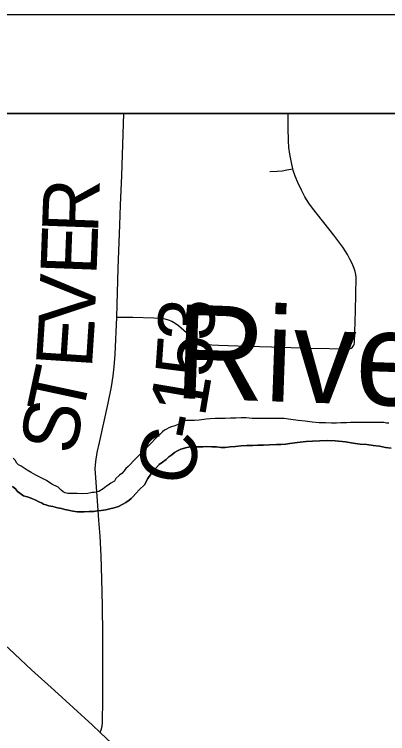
# Model space of a CAD drawing. Extents: x 0 to 34, y 0 to 22.
# Drawn here: x 25.806 to 26.184, y 20.273 to 21 of the extents above; entities that cross this region are included whole.
import ezdxf

# ---------------------------------------------------------------- set-up
doc = ezdxf.new("R2010")
doc.units = 0
for name, color, linetype in [('GM_X_County_Road', 7, 'Continuous'), ('GM_X_County_Road_Text', 7, 'Continuous'), ('GM_X_Major_River', 7, 'Continuous'), ('GM_X_Major_River_Text', 7, 'Continuous'), ('GM_X_State_Route', 7, 'Continuous'), ('GM_X_Township_Road', 7, 'Continuous'), ('SH_Data', 7, 'Continuous')]:
    doc.layers.add(name, color=color, linetype=linetype)

msp = doc.modelspace()

# ---------------------------------------------------------------- linework, layer by layer
at = {"layer": 'GM_X_County_Road'}
for points in [[(25.90978, 20.69411), (25.91088, 20.74343), (25.91264, 20.78688), (25.91344, 20.80738), (25.91462, 20.8372), (25.91676, 20.89997), (25.91676, 20.9)], [(25.8912, 20.49396), (25.88835, 20.532), (25.88788, 20.54084), (25.88833, 20.54822), (25.88979, 20.55737), (25.89217, 20.56749), (25.90082, 20.60711), (25.90424, 20.62359), (25.90597, 20.63468), (25.907, 20.64399), (25.90809, 20.65636), (25.90978, 20.69411)], [(25.89291, 20.27439), (25.89375, 20.27727), (25.89474, 20.28065), (25.89519, 20.28442), (25.89551, 20.30809), (25.89543, 20.33856), (25.89545, 20.37275), (25.89508, 20.40261), (25.89455, 20.42933), (25.89381, 20.45294), (25.89286, 20.47282), (25.89158, 20.48895), (25.8912, 20.49396)]]:
    msp.add_lwpolyline(points, dxfattribs=at)
at = {"layer": 'GM_X_Major_River'}
for points in [[(26.02465, 20.5919), (26.01933, 20.59166), (26.01401, 20.59179), (26.00907, 20.59154), (26.00412, 20.59128), (25.99994, 20.59101), (25.99308, 20.59005), (25.98813, 20.58979), (25.98357, 20.58953), (25.98015, 20.58961), (25.97786, 20.58929), (25.97516, 20.58746), (25.97169, 20.58565), (25.96824, 20.58422), (25.96479, 20.58317), (25.9621, 20.5821), (25.9598, 20.58102), (25.95787, 20.57993), (25.95593, 20.57808), (25.95359, 20.57586), (25.95088, 20.57365), (25.94814, 20.57069), (25.94502, 20.56735), (25.9415, 20.56364), (25.938, 20.56031), (25.93567, 20.5581), (25.92826, 20.55069), (25.9263, 20.54846), (25.92357, 20.54549), (25.92123, 20.54328), (25.9189, 20.54106), (25.91694, 20.53883), (25.9146, 20.53623), (25.91227, 20.53439), (25.90877, 20.53106), (25.90718, 20.52845), (25.90371, 20.52626), (25.901, 20.52443), (25.89907, 20.52334), (25.89597, 20.52076), (25.89134, 20.51784), (25.88676, 20.51682), (25.88486, 20.51687), (25.88027, 20.51584), (25.87533, 20.51559), (25.86963, 20.51573), (25.86432, 20.51587), (25.86014, 20.51598), (25.85749, 20.51642), (25.85525, 20.51762), (25.85339, 20.51919), (25.85043, 20.5223), (25.84405, 20.52549), (25.83844, 20.52905), (25.83319, 20.53184), (25.82756, 20.53427), (25.82307, 20.53704), (25.81895, 20.53942), (25.81596, 20.54139), (25.81297, 20.54337), (25.81035, 20.54495), (25.80849, 20.54652), (25.80667, 20.5496), (25.80482, 20.55155)], [(26.02465, 20.5919), (26.01933, 20.59166), (26.01401, 20.59179), (26.00907, 20.59154), (26.00412, 20.59128), (25.99994, 20.59101), (25.99308, 20.59005), (25.98813, 20.58979), (25.98357, 20.58953), (25.98015, 20.58961), (25.97786, 20.58929), (25.97516, 20.58746), (25.97169, 20.58565), (25.96824, 20.58422), (25.96479, 20.58317), (25.9621, 20.5821), (25.9598, 20.58102), (25.95787, 20.57993), (25.95593, 20.57808), (25.95359, 20.57586), (25.95088, 20.57365), (25.94814, 20.57069), (25.94502, 20.56735), (25.9415, 20.56364), (25.938, 20.56031), (25.93567, 20.5581), (25.92826, 20.55069), (25.9263, 20.54846), (25.92357, 20.54549), (25.92123, 20.54328), (25.9189, 20.54106), (25.91694, 20.53883), (25.9146, 20.53623), (25.91227, 20.53439), (25.90877, 20.53106), (25.90718, 20.52845), (25.90371, 20.52626), (25.901, 20.52443), (25.89907, 20.52334), (25.89597, 20.52076), (25.89134, 20.51784), (25.88676, 20.51682), (25.88486, 20.51687), (25.88027, 20.51584), (25.87533, 20.51559), (25.86963, 20.51573), (25.86432, 20.51587), (25.86014, 20.51598), (25.85749, 20.51642), (25.85525, 20.51762), (25.85339, 20.51919), (25.85043, 20.5223), (25.84405, 20.52549), (25.83844, 20.52905), (25.83319, 20.53184), (25.82756, 20.53427), (25.82307, 20.53704), (25.81895, 20.53942), (25.81596, 20.54139), (25.81297, 20.54337), (25.81035, 20.54495), (25.80849, 20.54652), (25.80667, 20.5496), (25.80482, 20.55155)], [(26.18484, 20.58708), (26.18256, 20.58713), (26.17991, 20.58758), (26.17725, 20.58765), (26.17422, 20.58773), (26.16168, 20.58766), (26.15636, 20.5878), (26.15066, 20.58756), (26.1461, 20.58768), (26.14192, 20.58741), (26.13621, 20.58717), (26.13203, 20.5869), (26.12672, 20.58703), (26.12064, 20.58719), (26.11419, 20.58735), (26.10736, 20.5879), (26.10017, 20.58885), (26.09298, 20.58979), (26.08578, 20.59073), (26.07897, 20.59166), (26.07176, 20.59184), (26.06415, 20.59166), (26.05351, 20.59155), (26.04668, 20.59172), (26.04062, 20.59226), (26.0353, 20.59239), (26.02998, 20.59214), (26.02465, 20.5919)], [(26.18484, 20.58708), (26.18256, 20.58713), (26.17991, 20.58758), (26.17725, 20.58765), (26.17422, 20.58773), (26.16168, 20.58766), (26.15636, 20.5878), (26.15066, 20.58756), (26.1461, 20.58768), (26.14192, 20.58741), (26.13621, 20.58717), (26.13203, 20.5869), (26.12672, 20.58703), (26.12064, 20.58719), (26.11419, 20.58735), (26.10736, 20.5879), (26.10017, 20.58885), (26.09298, 20.58979), (26.08578, 20.59073), (26.07897, 20.59166), (26.07176, 20.59184), (26.06415, 20.59166), (26.05351, 20.59155), (26.04668, 20.59172), (26.04062, 20.59226), (26.0353, 20.59239), (26.02998, 20.59214), (26.02465, 20.5919)], [(25.93242, 20.51984), (25.93748, 20.52464), (25.94106, 20.531), (25.94421, 20.53548), (25.94696, 20.53921), (25.9497, 20.54218), (25.95243, 20.54514), (25.95592, 20.54771), (25.9594, 20.55028), (25.96212, 20.55287), (25.96522, 20.55507), (25.96793, 20.55728), (25.97102, 20.5591), (25.97447, 20.56053), (25.9806, 20.56227), (25.9825, 20.5626), (25.98479, 20.56292), (25.98745, 20.56285), (25.99012, 20.56317), (25.99315, 20.56309), (25.99657, 20.563), (26.00038, 20.56329), (26.00569, 20.56315), (26.01063, 20.56303), (26.01479, 20.56254), (26.01935, 20.56242), (26.0243, 20.56306), (26.02963, 20.56331), (26.03534, 20.56392), (26.04105, 20.56453), (26.04713, 20.56438), (26.05245, 20.56462), (26.05816, 20.56486), (26.06424, 20.56508), (26.07108, 20.56529), (26.07565, 20.56555), (26.08059, 20.56581), (26.08479, 20.56646), (26.08974, 20.56709), (26.09508, 20.56772), (26.10117, 20.56832), (26.10764, 20.56892), (26.11486, 20.56911), (26.12285, 20.56929), (26.13044, 20.5691), (26.14105, 20.56807), (26.14861, 20.56674), (26.15581, 20.5658), (26.16263, 20.56524), (26.16907, 20.56432), (26.17551, 20.56378), (26.18155, 20.56248), (26.18723, 20.56158)], [(26.18723, 20.56158), (26.18155, 20.56248), (26.17551, 20.56378), (26.16907, 20.56432), (26.16263, 20.56524), (26.15581, 20.5658), (26.14861, 20.56674), (26.14105, 20.56807), (26.13044, 20.5691), (26.12285, 20.56929), (26.11486, 20.56911), (26.10764, 20.56892), (26.10117, 20.56832), (26.09508, 20.56772), (26.08974, 20.56709), (26.08479, 20.56646), (26.08059, 20.56581), (26.07565, 20.56555), (26.07108, 20.56529), (26.06424, 20.56508), (26.05816, 20.56486), (26.05245, 20.56462), (26.04713, 20.56438), (26.04105, 20.56453), (26.03534, 20.56392), (26.02963, 20.56331), (26.0243, 20.56306), (26.01935, 20.56242), (26.01479, 20.56254), (26.01063, 20.56303), (26.00569, 20.56315), (26.00038, 20.56329), (25.99657, 20.563), (25.99315, 20.56309), (25.99012, 20.56317), (25.98745, 20.56285), (25.98479, 20.56292), (25.9825, 20.5626), (25.9806, 20.56227), (25.97447, 20.56053), (25.97102, 20.5591), (25.96793, 20.55728), (25.96522, 20.55507), (25.96212, 20.55287), (25.9594, 20.55028), (25.95592, 20.54771), (25.95243, 20.54514), (25.9497, 20.54218), (25.94696, 20.53921), (25.94421, 20.53548), (25.94106, 20.531), (25.93748, 20.52464), (25.93242, 20.51984)], [(25.8041, 20.52309), (25.80708, 20.52074), (25.80929, 20.51803), (25.81526, 20.5137), (25.81752, 20.51288), (25.82016, 20.51206), (25.82429, 20.51043), (25.82768, 20.50921), (25.83068, 20.50761), (25.83331, 20.50641), (25.83556, 20.50521), (25.83782, 20.5044), (25.84083, 20.50356), (25.84499, 20.50269), (25.84952, 20.50144), (25.85368, 20.50058), (25.85707, 20.49973), (25.86199, 20.49885), (25.86501, 20.49801), (25.86765, 20.49756), (25.86993, 20.49751), (25.87259, 20.49744), (25.87676, 20.49733), (25.88171, 20.49759), (25.88628, 20.49785), (25.88971, 20.49852), (25.8939, 20.4988), (25.89847, 20.49944), (25.90268, 20.50047), (25.90688, 20.5015), (25.91147, 20.50291), (25.91571, 20.50508), (25.91879, 20.5069), (25.92227, 20.50908), (25.92421, 20.51093), (25.92616, 20.51278), (25.92889, 20.51575), (25.93242, 20.51984)], [(25.93242, 20.51984), (25.92889, 20.51575), (25.92616, 20.51278), (25.92421, 20.51093), (25.92227, 20.50908), (25.91879, 20.5069), (25.91571, 20.50508), (25.91147, 20.50291), (25.90688, 20.5015), (25.90268, 20.50047), (25.89847, 20.49944), (25.8939, 20.4988), (25.88971, 20.49852), (25.88628, 20.49785), (25.88171, 20.49759), (25.87676, 20.49733), (25.87259, 20.49744), (25.86993, 20.49751), (25.86765, 20.49756), (25.86501, 20.49801), (25.86199, 20.49885), (25.85707, 20.49973), (25.85368, 20.50058), (25.84952, 20.50144), (25.84499, 20.50269), (25.84083, 20.50356), (25.83782, 20.5044), (25.83556, 20.50521), (25.83331, 20.50641), (25.83068, 20.50761), (25.82768, 20.50921), (25.82429, 20.51043), (25.82016, 20.51206), (25.81752, 20.51288), (25.81526, 20.5137), (25.80929, 20.51803), (25.80708, 20.52074), (25.8041, 20.52309)]]:
    msp.add_lwpolyline(points, dxfattribs=at)
at = {"layer": 'GM_X_State_Route'}
msp.add_lwpolyline([(25.7576, 20.39756), (25.76134, 20.39419), (25.80075, 20.35897), (25.82345, 20.33775), (25.84654, 20.31694), (25.88515, 20.28176), (25.89291, 20.27439), (25.90455, 20.26333), (25.9301, 20.2388), (25.9387, 20.23059), (25.9419, 20.22759)], dxfattribs=at)
at = {"layer": 'GM_X_Township_Road'}
for points in [[(28.91036, 20.9), (23.51667, 20.9)], [(26.08776, 20.84404), (26.08623, 20.85023), (26.08455, 20.85877), (26.08366, 20.86555), (26.08321, 20.87236), (26.08302, 20.88542), (26.08302, 20.9)], [(26.06454, 20.84133), (26.07191, 20.84154), (26.07707, 20.84208), (26.08164, 20.8429), (26.08776, 20.84404)], [(26.14796, 20.66369), (26.14878, 20.66473), (26.14938, 20.66584), (26.1497, 20.66682), (26.14991, 20.668), (26.15114, 20.70056), (26.15175, 20.73416), (26.15149, 20.73731), (26.15083, 20.74027), (26.14965, 20.74339), (26.14832, 20.74673), (26.14708, 20.74949), (26.14546, 20.75272), (26.1429, 20.75722), (26.13826, 20.76477), (26.12909, 20.77677), (26.10744, 20.80429), (26.10385, 20.80936), (26.0999, 20.81569), (26.09635, 20.82225), (26.09265, 20.83013), (26.09011, 20.83648), (26.08817, 20.84238), (26.08776, 20.84404)], [(25.90978, 20.69411), (25.92599, 20.694), (25.94705, 20.6934), (25.95338, 20.69299), (25.95806, 20.69226), (25.96161, 20.69127), (25.96522, 20.68988), (25.96876, 20.68799), (25.97197, 20.68569), (25.97477, 20.68314), (25.98275, 20.67615), (25.9867, 20.67279), (25.98975, 20.67016), (25.99205, 20.66876), (25.99432, 20.66809), (25.99907, 20.66708), (26.00578, 20.66621), (26.01254, 20.66581), (26.04175, 20.66486), (26.06618, 20.66409), (26.10598, 20.66289), (26.14326, 20.66197), (26.14495, 20.66215), (26.14601, 20.66246), (26.14676, 20.66283), (26.14796, 20.66369)]]:
    msp.add_lwpolyline(points, dxfattribs=at)
at = {"layer": 'SH_Data'}
for points in [[(23.41667, 21), (30.41667, 21), (30.41667, 14), (23.41667, 14)], [(23.51667, 20.9), (30.31667, 20.9), (30.31667, 14.1), (23.51667, 14.1)]]:
    msp.add_lwpolyline(points, close=True, dxfattribs=at)

# ---------------------------------------------------------------- texts
at = {"layer": 'GM_X_County_Road_Text'}
for s, rotation, p in [('R', 87.88449, (25.89061, 20.77826)), ('E', 87.88434, (25.88904, 20.73579)), ('V', 87.87106, (25.88718, 20.68581)), ('3', 87.90574, (26.00766, 20.66955)), ('E', 86.23105, (25.8843, 20.64163)), ('5', 86.03581, (26.00514, 20.63261)), ('T', 77.89117, (25.87414, 20.59114)), ('1', 80.38385, (25.99856, 20.59203)), ('S', 79.31671, (25.8671, 20.55384)), ('-', 78.67928, (25.99365, 20.56734)), ('C', 78.58864, (25.9844, 20.52149))]:
    msp.add_text(s, height=0.05682, rotation=rotation, dxfattribs=at).set_placement(p)
at = {"layer": 'GM_X_Major_River_Text'}
msp.add_text('River', height=0.094748, rotation=358.04489, dxfattribs=at).set_placement((25.96697, 20.61241))

doc.saveas('drawing.dxf')
